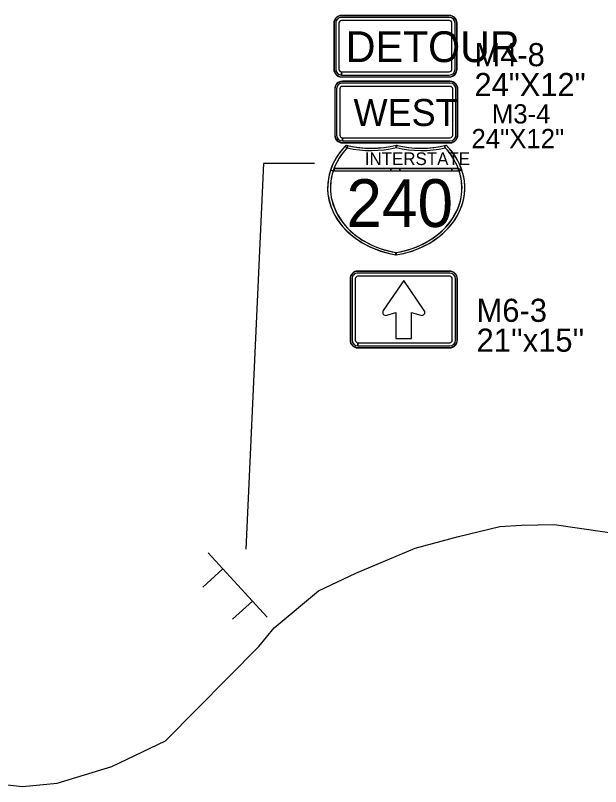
# Model space of a CAD drawing. Extents: x 886234 to 968767, y 455416 to 684046.
# Drawn here: x 910248 to 912527, y 469657 to 472663 of the extents above; entities that cross this region are included whole.
import ezdxf

# ---------------------------------------------------------------- set-up
doc = ezdxf.new("R2010")
doc.units = 0
for name, color, linetype in [('TC DEV SIGN', 7, 'Continuous'), ('TC DEV SIGN BLACK 239', 7, 'Continuous'), ('TC DEV SIGN BLACK ZERO', 7, 'Continuous'), ('TC DEV SIGN ORANGE', 7, 'Continuous'), ('TC DEV SIGN WHITE', 7, 'Continuous'), ('TC LABEL TEXT', 7, 'Continuous')]:
    doc.layers.add(name, color=color, linetype=linetype)

msp = doc.modelspace()

# ---------------------------------------------------------------- linework, layer by layer
at = {"layer": 'TC DEV SIGN'}
for p, q in [((911113.2, 470442.9), (910998.4, 470568)), ((911055.8, 470505.5), (910978.3, 470434.3)), ((911228, 470317.8), (911113.2, 470442.9)), ((911170.6, 470380.4), (911093.1, 470309.2))]:
    msp.add_line(p, q, dxfattribs=at)
at = {"layer": 'TC DEV SIGN BLACK 239'}
for p, q in [((911941.4, 472398.6), (911521.4, 472398.6)), ((911498.9, 472376.1), (911498.9, 472196.1)), ((911511.4, 472376.1), (911511.4, 472196.1)), ((911941.4, 472386.1), (911521.4, 472386.1)), ((911951.4, 472196.1), (911951.4, 472376.1)), ((911963.9, 472196.1), (911963.9, 472376.1)), ((911521.4, 472173.6), (911521.4, 472186.1)), ((911521.5, 472186.1), (911941.4, 472186.1)), ((911521.5, 472186.1), (911521.5, 472173.6)), ((911521.5, 472173.6), (911941.4, 472173.6)), ((911939.5, 471658.8), (911581.7, 471658.8)), ((911939.5, 471646.1), (911581.7, 471646.1)), ((911558.9, 471636), (911558.9, 471397.4)), ((911571.6, 471636), (911571.6, 471397.4)), ((911949.6, 471397.4), (911949.6, 471636)), ((911962.3, 471397.4), (911962.3, 471636)), ((911581.7, 471374.6), (911581.7, 471387.3)), ((911581.8, 471387.3), (911939.5, 471387.3)), ((911581.8, 471387.3), (911581.8, 471374.6)), ((911581.8, 471374.6), (911939.5, 471374.6))]:
    msp.add_line(p, q, dxfattribs=at)
for points in [[(911840.7, 471512.5), (911760.6, 471629.1), (911680.6, 471512.5)], [(911840.7, 471512.5), (911760.6, 471629.1), (911680.6, 471512.5)], [(911840.7, 471512.5), (911760.6, 471629.1), (911680.6, 471512.5)], [(911694.3, 471494), (911730.2, 471505.3), (911730.2, 471403), (911791, 471403)], [(911694.3, 471494), (911730.2, 471505.3), (911730.2, 471403), (911791, 471403)], [(911694.3, 471494), (911730.2, 471505.3), (911730.2, 471403), (911791, 471403)], [(911791, 471403), (911791, 471505.3), (911827, 471494)], [(911791, 471403), (911791, 471505.3), (911827, 471494)], [(911791, 471403), (911791, 471505.3), (911827, 471494)]]:
    msp.add_lwpolyline(points, dxfattribs=at)
for centre, start, end in [((911690.6, 471505.5), 145.5508, 287.601), ((911690.6, 471505.5), 145.5508, 287.601), ((911690.6, 471505.5), 145.5508, 287.601), ((911830.6, 471505.5), 252.399, 34.4492), ((911830.6, 471505.5), 252.399, 34.4492), ((911830.6, 471505.5), 252.399, 34.4492)]:
    msp.add_arc(centre, 12.2, start, end, dxfattribs=at)
for centre, major_axis, start_param, end_param in [((911521.4, 472376.1), (22.5, 0), 1.570796, 3.141593), ((911941.4, 472376.1), (22.5, 0), 0, 1.570796), ((911521.4, 472376.1), (10, 0), 1.570796, 3.141593), ((911941.4, 472376.1), (10, 0), 0, 1.570796), ((911521.4, 472196.1), (22.5, 0), 3.141593, 4.712389), ((911521.4, 472196.1), (10, 0), 3.141593, 4.712389), ((911941.4, 472196.1), (22.5, 0), 4.712389, 6.283185), ((911941.4, 472196.1), (10, 0), 4.712389, 6.283185), ((911581.7, 471636), (22.8, 0), 1.570796, 3.141593), ((911581.7, 471636), (10.1, 0), 1.570796, 3.141593), ((911939.5, 471636), (22.8, 0), 0, 1.570796), ((911939.5, 471636), (10.1, 0), 0, 1.570796), ((911581.7, 471397.4), (22.8, 0), 3.141593, 4.712389), ((911581.7, 471397.4), (10.1, 0), 3.141593, 4.712389), ((911939.5, 471397.4), (22.8, 0), 4.712389, 6.283185), ((911939.5, 471397.4), (10.1, 0), 4.712389, 6.283185)]:
    msp.add_ellipse(centre, major_axis=major_axis, ratio=0.999865, start_param=start_param, end_param=end_param, dxfattribs=at)
at = {"layer": 'TC DEV SIGN BLACK ZERO'}
for p, q in [((911938, 472662.7), (911518, 472662.7)), ((911518, 472661.4), (911518, 472661.4)), ((911938, 472661.4), (911518, 472661.4)), ((911938, 472661.4), (911938, 472661.4)), ((911488, 472632.7), (911488, 472452.7)), ((911489.2, 472632.7), (911489.2, 472452.7)), ((911489.2, 472632.7), (911489.2, 472632.7)), ((911495.5, 472632.7), (911495.5, 472452.7)), ((911508, 472632.7), (911508, 472452.7)), ((911938, 472655.2), (911518, 472655.2)), ((911938, 472642.7), (911518, 472642.7)), ((911948, 472452.7), (911948, 472632.7)), ((911960.5, 472452.7), (911960.5, 472632.7)), ((911966.8, 472632.7), (911966.8, 472632.7)), ((911966.8, 472452.7), (911966.8, 472632.7)), ((911968, 472452.7), (911968, 472632.7)), ((911489.2, 472452.7), (911489.2, 472452.7)), ((911966.8, 472452.7), (911966.8, 472452.7)), ((911518, 472430.2), (911518, 472442.7)), ((911518, 472422.7), (911518, 472423.9)), ((911518, 472423.9), (911518, 472423.9)), ((911518, 472423.9), (911938, 472423.9)), ((911518, 472423.9), (911518, 472422.7)), ((911518, 472422.7), (911938, 472422.7)), ((911518.1, 472442.7), (911938, 472442.7)), ((911518.1, 472442.7), (911518.1, 472430.2)), ((911518.1, 472430.2), (911938, 472430.2)), ((911938, 472423.9), (911938, 472423.9)), ((911941.4, 472406.1), (911521.4, 472406.1)), ((911521.4, 472404.9), (911521.4, 472404.9)), ((911941.4, 472404.9), (911521.4, 472404.9)), ((911941.4, 472404.9), (911941.4, 472404.9)), ((911491.4, 472376.1), (911491.4, 472196.1)), ((911492.6, 472376.1), (911492.6, 472196.1)), ((911492.6, 472376.1), (911492.6, 472376.1)), ((911970.2, 472376.1), (911970.2, 472376.1)), ((911970.2, 472196.1), (911970.2, 472376.1)), ((911971.4, 472196.1), (911971.4, 472376.1)), ((911492.6, 472196.1), (911492.6, 472196.1)), ((911970.2, 472196.1), (911970.2, 472196.1)), ((911521.4, 472166.1), (911521.4, 472167.4)), ((911521.4, 472167.4), (911521.4, 472167.4)), ((911521.4, 472167.4), (911941.4, 472167.4)), ((911521.4, 472167.4), (911521.4, 472166.1)), ((911521.4, 472166.1), (911941.4, 472166.1)), ((911540.1, 472146.6), (911543.1, 472155.2)), ((911731.4, 472147.6), (911731.1, 472156.9)), ((911731.4, 472148.3), (911731.1, 472156.9)), ((911919.2, 472155.2), (911922.2, 472146.6)), ((911941.4, 472167.4), (911941.4, 472167.4)), ((911488.8, 472065.7), (911973.5, 472065.7)), ((911710.7, 472065.7), (911488.8, 472065.7)), ((911745.9, 472065.7), (911710.7, 472065.7)), ((911947.3, 472065.7), (911745.9, 472065.7)), ((911973.5, 472065.7), (911947.3, 472065.7)), ((911987.4, 472059.1), (911973.5, 472065.7)), ((911485.7, 472056.8), (911976.6, 472056.8)), ((911485.7, 472056.8), (911488.8, 472056.8)), ((911488.8, 472056.8), (911710.7, 472056.8)), ((911710.7, 472056.8), (911745.9, 472056.8)), ((911745.9, 472056.8), (911947.3, 472056.8)), ((911947.3, 472056.8), (911973.5, 472056.8)), ((911976.4, 472057.4), (911973.5, 472056.8)), ((911973.5, 472056.8), (911976.6, 472056.8)), ((911464, 471992.5), (911464, 471989.9)), ((911998.3, 471989.8), (911998.3, 471992.6)), ((911731.1, 471729.4), (911731.1, 471738.5)), ((911939.5, 471666.4), (911581.7, 471666.4)), ((911581.7, 471665.1), (911581.7, 471665.2)), ((911939.5, 471665.1), (911581.7, 471665.2)), ((911939.5, 471665.1), (911939.5, 471665.1)), ((911551.3, 471636), (911551.3, 471397.4)), ((911552.6, 471636), (911552.5, 471397.4)), ((911552.6, 471636), (911552.6, 471636)), ((911968.7, 471636), (911968.7, 471636)), ((911968.7, 471397.4), (911968.7, 471636)), ((911969.9, 471397.4), (911969.9, 471636)), ((911552.6, 471397.4), (911552.5, 471397.4)), ((911581.7, 471367), (911581.7, 471368.3)), ((911581.7, 471368.3), (911581.7, 471368.3)), ((911581.7, 471368.3), (911939.5, 471368.3)), ((911581.7, 471368.3), (911581.7, 471367)), ((911939.5, 471368.3), (911939.5, 471368.3)), ((911968.7, 471397.4), (911968.7, 471397.4)), ((911581.7, 471367), (911939.5, 471367))]:
    msp.add_line(p, q, dxfattribs=at)
for points in [[(911531.2, 472152), (911540.1, 472146.6)], [(911540.1, 472146.6), (911531.2, 472152)], [(911536, 472156.9), (911535.9, 472156.9), (911535.9, 472156.9)], [(911543.1, 472155.2), (911540.1, 472146.6)], [(911731.4, 472156.8), (911731.4, 472148.3), (911734.6, 472156.1)], [(911734.6, 472156.1), (911731.4, 472147.6)], [(911922.2, 472146.6), (911919.2, 472155.2)], [(911926.3, 472156.9), (911926.3, 472156.9), (911926.3, 472156.9)], [(911731.1, 472147.6), (911731.4, 472148.3)], [(911474.9, 472059.1), (911485.7, 472056.8)], [(911485.7, 472056.8), (911474.9, 472059.1)], [(911488.8, 472065.7), (911488.8, 472056.8)], [(911488.8, 472056.8), (911488.8, 472065.7)], [(911710.7, 472056.8), (911710.7, 472065.7)], [(911710.7, 472065.7), (911710.7, 472056.8)], [(911745.9, 472065.7), (911745.9, 472056.8)], [(911745.9, 472056.8), (911745.9, 472065.7)], [(911947.3, 472056.8), (911947.3, 472065.7)], [(911947.3, 472065.7), (911947.3, 472056.8)], [(911973.5, 472065.7), (911987.4, 472059.1)], [(911973.5, 472056.8), (911973.5, 472065.7)], [(911973.5, 472065.7), (911973.5, 472056.8), (911976.4, 472057.4), (911973.5, 472065.7)], [(911987.4, 472059.1), (911976.6, 472056.8)], [(911976.6, 472056.8), (911987.4, 472059.1)], [(911976.6, 472056.8), (911976.4, 472057.4)], [(911728.8, 471729.8), (911731.1, 471738.5)], [(911731.1, 471738.5), (911728.8, 471729.8), (911731.1, 471729.4)], [(911731.1, 471738.5), (911731.1, 471729.4)]]:
    msp.add_lwpolyline(points, dxfattribs=at)
for centre, major_axis, ratio, start_param, end_param in [((911518, 472632.7), (30, 0), 0.999865, 1.570796, 3.141593), ((911518, 472632.7), (28.8, 0), 0.999865, 1.570796, 3.141593), ((911938, 472632.7), (30, 0), 0.999865, 0, 1.570796), ((911938, 472632.7), (28.8, 0), 0.999865, 0, 1.570796), ((911518, 472632.7), (22.5, 0), 0.999865, 1.570796, 3.141593), ((911518, 472632.7), (10, 0), 0.999865, 1.570796, 3.141593), ((911938, 472632.7), (22.5, 0), 0.999865, 0, 1.570796), ((911938, 472632.7), (10, 0), 0.999865, 0, 1.570796), ((911518, 472452.7), (30, 0), 0.999865, 3.141593, 4.712389), ((911518, 472452.7), (28.8, 0), 0.999865, 3.141593, 4.712389), ((911518, 472452.7), (22.5, 0), 0.999865, 3.141593, 4.712389), ((911518, 472452.7), (10, 0), 0.999865, 3.141593, 4.712389), ((911938, 472452.7), (22.5, 0), 0.999865, 4.712389, 6.283185), ((911938, 472452.7), (10, 0), 0.999865, 4.712389, 6.283185), ((911938, 472452.7), (30, 0), 0.999865, 4.712389, 6.283185), ((911938, 472452.7), (28.8, 0), 0.999865, 4.712389, 6.283185), ((911521.4, 472376.1), (30, 0), 0.999865, 1.570796, 3.141593), ((911521.4, 472376.1), (28.8, 0), 0.999865, 1.570796, 3.141593), ((911941.4, 472376.1), (30, 0), 0.999865, 0, 1.570796), ((911941.4, 472376.1), (28.8, 0), 0.999865, 0, 1.570796), ((911521.4, 472196.1), (30, 0), 0.999865, 3.141593, 4.712389), ((911521.4, 472196.1), (28.8, 0), 0.999865, 3.141593, 4.712389), ((911941.4, 472196.1), (30, 0), 0.999865, 4.712389, 6.283185), ((911941.4, 472196.1), (28.8, 0), 0.999865, 4.712389, 6.283185), ((911797.9, 471991.2), (-334, 0), 0.800002, 5.614188, 7.652625), ((911797.9, 471991.2), (-334, 0), 0.800002, 5.637358, 6.026219), ((911797.9, 471991.2), (-334, 0), 0.800002, 5.614216, 5.637358), ((911633.6, 472412.4), (334, 0), 0.800002, 4.415792, 5.008922), ((911633.6, 472412.4), (334, 0), 0.800002, 4.415856, 4.438209), ((911633.6, 472412.4), (334, 0), 0.800002, 4.438209, 5.008909), ((911828.7, 472412.4), (334, 0), 0.800002, 4.415856, 5.008986), ((911664.3, 471991.2), (334, 0), 0.800002, 4.913746, 6.952183), ((911828.7, 472412.4), (334, 0), 0.800002, 4.416709, 4.426515), ((911828.7, 472412.4), (334, 0), 0.800002, 4.426515, 4.986569), ((911828.7, 472412.4), (334, 0), 0.800002, 4.986569, 5.008922), ((911664.3, 471991.2), (334, 0), 0.800002, 0.256966, 0.66897), ((911797.9, 471991.2), (-322.9, 0), 0.800002, 5.637358, 7.64558), ((911797.9, 471991.2), (-322.9, 0), 0.800002, 5.637358, 6.026219), ((911633.6, 472412.4), (345.1, 0), 0.800002, 4.438209, 4.999074), ((911633.6, 472412.4), (345.1, 0), 0.800002, 4.438209, 4.999074), ((911828.7, 472412.4), (345.1, 0), 0.800002, 4.425704, 4.986569), ((911664.3, 471991.2), (322.9, 0), 0.800002, 4.920791, 6.929013), ((911828.9, 472412), (344.6, 0), 0.800002, 4.425686, 4.986568), ((911664.3, 471991.2), (322.9, 0), 0.800002, 0.292795, 0.645828), ((911797.9, 471991.2), (-334, 0), 0.800002, 6.026219, 6.278259), ((911797.9, 471991.2), (-322.9, 0), 0.800002, 5.99039, 6.026219), ((911664.3, 471991.2), (322.9, 0), 0.800002, 0.256966, 0.292795), ((911664.3, 471991.2), (334, 0), 0.800002, 0.005231, 0.256966), ((911796.4, 471990.4), (-321.6, 0), 0.800002, 6.022151, 7.649781), ((911665.9, 471990.4), (321.6, 0), 0.800002, 4.916934, 6.544356), ((911797.9, 471991.2), (-334, 0), 0.800002, 0.004927, 1.362388), ((911664.3, 471991.2), (334, 0), 0.800002, 4.913748, 6.277955), ((911664.3, 471991.2), (322.9, 0), 0.800002, 4.920791, 4.921138), ((911797.9, 471991.2), (-334, 0), 0.800002, 1.36935, 1.369438), ((911664.3, 471991.2), (334, 0), 0.800002, 4.913747, 4.913748), ((911581.7, 471636), (30.4, 0), 0.999865, 1.570796, 3.141593), ((911581.7, 471636), (29.2, 0), 0.999865, 1.570796, 3.141593), ((911939.5, 471636), (30.4, 0), 0.999865, 0, 1.570796), ((911939.5, 471636), (29.2, 0), 0.999865, 0, 1.570796), ((911581.7, 471397.4), (30.4, 0), 0.999865, 3.141593, 4.712389), ((911581.7, 471397.4), (29.2, 0), 0.999865, 3.141593, 4.712389), ((911939.5, 471397.4), (30.4, 0), 0.999865, 4.712389, 6.283185), ((911939.5, 471397.4), (29.2, 0), 0.999865, 4.712389, 6.283185)]:
    msp.add_ellipse(centre, major_axis=major_axis, ratio=ratio, start_param=start_param, end_param=end_param, dxfattribs=at)
at = {"layer": 'TC DEV SIGN ORANGE'}
for p, q in [((911938, 472662.7), (911518, 472662.7)), ((911488, 472632.7), (911488, 472452.7)), ((911968, 472452.7), (911968, 472632.7)), ((911518, 472422.7), (911938, 472422.7))]:
    msp.add_line(p, q, dxfattribs=at)
for centre, start_param, end_param in [((911518, 472632.7), 1.570796, 3.141593), ((911938, 472632.7), 0, 1.570796), ((911518, 472452.7), 3.141593, 4.712389), ((911938, 472452.7), 4.712389, 6.283185)]:
    msp.add_ellipse(centre, major_axis=(30, 0), ratio=0.999865, start_param=start_param, end_param=end_param, dxfattribs=at)
at = {"layer": 'TC DEV SIGN WHITE'}
for p, q in [((911941.4, 472406.1), (911521.4, 472406.1)), ((911491.4, 472376.1), (911491.4, 472196.1)), ((911971.4, 472196.1), (911971.4, 472376.1)), ((911521.4, 472166.1), (911941.4, 472166.1)), ((911939.5, 471666.4), (911581.7, 471666.4)), ((911551.3, 471636), (911551.3, 471397.4)), ((911969.9, 471397.4), (911969.9, 471636)), ((911581.7, 471367), (911939.5, 471367))]:
    msp.add_line(p, q, dxfattribs=at)
for centre, major_axis, start_param, end_param in [((911521.4, 472376.1), (30, 0), 1.570796, 3.141593), ((911941.4, 472376.1), (30, 0), 0, 1.570796), ((911521.4, 472196.1), (30, 0), 3.141593, 4.712389), ((911941.4, 472196.1), (30, 0), 4.712389, 6.283185), ((911581.7, 471636), (30.4, 0), 1.570796, 3.141593), ((911939.5, 471636), (30.4, 0), 0, 1.570796), ((911581.7, 471397.4), (30.4, 0), 3.141593, 4.712389), ((911939.5, 471397.4), (30.4, 0), 4.712389, 6.283185)]:
    msp.add_ellipse(centre, major_axis=major_axis, ratio=0.999865, start_param=start_param, end_param=end_param, dxfattribs=at)
at = {"layer": 'TC LABEL TEXT'}
for points in [[(911412.7, 472085.2), (911214.3, 472085.2), (911144.6, 470583.1)], [(911255.9, 470276.2), (911429, 470420.7), (911573.5, 470488.6), (911805, 470586.2), (911973.5, 470631.3), (912135.4, 470671.4), (912219.9, 470676.6), (912347, 470678.4), (912731.8, 470623.4), (913365.8, 470460.9), (913616.7, 470416), (913877.1, 470406.3), (914283.8, 470436.6), (914409.4, 470437.1), (914625.9, 470447.5), (914828.6, 470438.3), (915003, 470397.9), (915279, 470320), (915454.7, 470262.6), (915634, 470177.3), (915731, 470111.5), (915875.5, 470024.3), (915960.8, 469970.3), (916138.7, 469877.4)], [(909509.7, 469912.3), (909635.5, 469843.4), (909806.4, 469776.3), (909989.1, 469714.2), (910144.5, 469672.4), (910275.2, 469657.3), (910410.7, 469670.7), (910623.5, 469736.1), (910832.6, 469834.9), (911195.7, 470203.4), (911255.9, 470276.2)]]:
    msp.add_lwpolyline(points, dxfattribs=at)

# ---------------------------------------------------------------- texts
at = {"layer": 'TC DEV SIGN BLACK 239'}
msp.add_text('WEST', height=105, rotation=360, dxfattribs=at).set_placement((911565, 472231.8))
at = {"layer": 'TC DEV SIGN BLACK ZERO'}
for s, height, p in [('DETOUR', 120, (911534.6, 472480.8)), ('M4-8', 90, (912035.9, 472464.7)), ('24"X12"', 90, (912035.9, 472348.3)), ('INTERSTATE', 49.28, (911608.7, 472079.5)), ('240', 186.16, (911537.3, 471838.2)), ('M6-3', 90, (912044.3, 471468.4)), ("21''x15''", 90, (912044.3, 471352))]:
    msp.add_text(s, height=height, rotation=360, dxfattribs=at).set_placement(p)
at = {"layer": 'TC LABEL TEXT'}
for s, p in [('M3-4', (912103.9, 472241.5)), ('24"X12"', (912024.4, 472145.2))]:
    msp.add_text(s, height=75, dxfattribs=at).set_placement(p)

doc.saveas('drawing.dxf')
